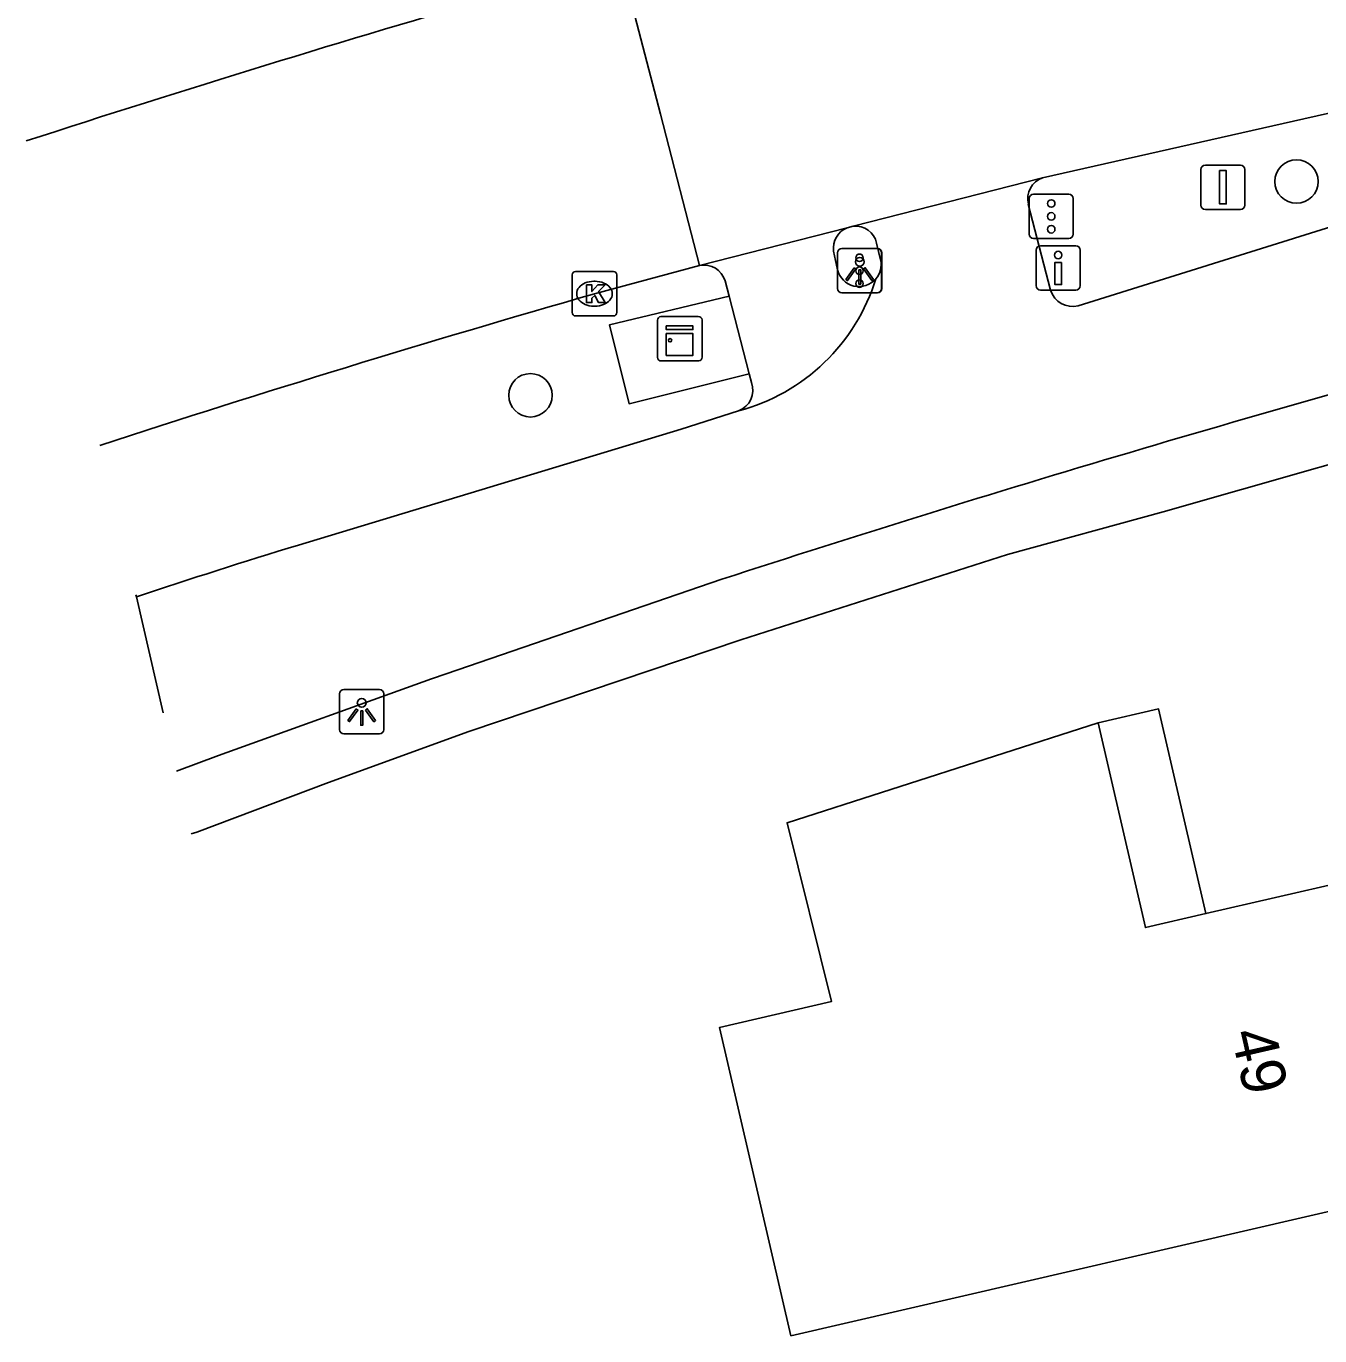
# Model space of a CAD drawing. Extents: x 156414 to 157775, y 382335 to 383765.
# Drawn here: x 156630.05 to 156659.19, y 382874.07 to 382903.56 of the extents above; entities that cross this region are included whole.
import ezdxf

# ---------------------------------------------------------------- set-up
doc = ezdxf.new("R2010")
doc.units = 0
for name, color, linetype in [('IMGEO_Boom', 7, 'Continuous'), ('IMGEO_Drukknoppaal', 7, 'Continuous'), ('IMGEO_Fietspad_gesloten', 7, 'Continuous'), ('IMGEO_Kast', 7, 'Continuous'), ('IMGEO_Kolk', 7, 'Continuous'), ('IMGEO_Lichtpunt', 7, 'Continuous'), ('IMGEO_OVBaan_gesloten', 7, 'Continuous'), ('IMGEO_Pand', 7, 'Continuous'), ('IMGEO_Pand_nummerreeks', 7, 'Continuous'), ('IMGEO_Pand_overbouw', 7, 'Continuous'), ('IMGEO_Verkeersbordpaal', 7, 'Continuous'), ('IMGEO_Verkeersregelinstallatiepaal', 7, 'Continuous'), ('IMGEO_Voetpad_open', 7, 'Continuous')]:
    doc.layers.add(name, color=color, linetype=linetype)

msp = doc.modelspace()

# ---------------------------------------------------------------- linework, layer by layer
at = {"layer": 'IMGEO_Boom'}
for centre in [(156658.661, 382900.059), (156641.409, 382895.246)]:
    msp.add_circle(centre, 0.489, dxfattribs=at)
at = {"layer": 'IMGEO_Drukknoppaal'}
for p, q in [((156652.799, 382897.715), (156652.799, 382898.515)), ((156652.799, 382898.515), (156652.799, 382897.715)), ((156652.899, 382898.615), (156653.689, 382898.615)), ((156653.689, 382898.615), (156652.899, 382898.615)), ((156653.789, 382898.515), (156653.789, 382897.715)), ((156653.789, 382897.715), (156653.789, 382898.515)), ((156653.689, 382897.615), (156652.899, 382897.615)), ((156652.899, 382897.615), (156653.689, 382897.615))]:
    msp.add_line(p, q, dxfattribs=at)
msp.add_lwpolyline([(156653.369, 382898.24), (156653.369, 382897.74), (156653.219, 382897.74), (156653.219, 382898.24), (156653.369, 382898.24)], dxfattribs=at)
msp.add_circle((156653.294, 382898.405), 0.085, dxfattribs=at)
for centre, start, end in [((156652.899, 382898.515), 90, 180), ((156652.899, 382898.515), 90, 180), ((156653.689, 382898.515), 0, 90), ((156653.689, 382898.515), 360, 90), ((156652.899, 382897.715), 180, 270), ((156652.899, 382897.715), 180, 270), ((156653.689, 382897.715), 270, 0), ((156653.689, 382897.715), 270, 0)]:
    msp.add_arc(centre, 0.1, start, end, dxfattribs=at)
at = {"layer": 'IMGEO_Fietspad_gesloten'}
for points in [[(156667.356, 382901.52), (156653.745, 382897.261)], [(156653.124, 382897.612), (156652.622, 382899.55)], [(156649.206, 382898.672), (156649.296, 382898.294)], [(156646.098, 382894.894), (156644.805, 382894.481), (156636.186, 382891.875)], [(156633.442, 382886.785), (156634.383, 382887.139), (156639.183, 382888.859), (156639.511, 382888.974), (156645.723, 382891.105)], [(156632.536, 382890.706), (156632.525, 382890.752)], [(156632.536, 382890.706), (156633.139, 382888.095)]]:
    msp.add_lwpolyline(points, dxfattribs=at)
for centre, radius, start, end in [((156653.113, 382899.669), 0.505, 109.9269, 193.5983), ((156648.722, 382898.559), 0.497, 13.1695, 94.8535), ((156648.807, 382898.193), 0.5, 319.7399, 11.6794), ((156644.961, 382899.167), 4.421, 284.9015, 342.9452), ((156653.618, 382897.761), 0.516, 196.8081, 284.2401), ((156758.708, 382543.808), 365.213, 105.00057, 108.02104), ((156677.031, 382758.061), 139.909, 106.97411, 108.54371)]:
    msp.add_arc(centre, radius, start, end, dxfattribs=at)
at = {"layer": 'IMGEO_Kast'}
for p, q in [((156644.274, 382896.095), (156644.274, 382896.936)), ((156644.274, 382896.936), (156644.274, 382896.095)), ((156644.349, 382897.02), (156645.19, 382897.02)), ((156645.19, 382897.02), (156644.349, 382897.02)), ((156645.274, 382896.945), (156645.274, 382896.104)), ((156645.274, 382896.104), (156645.274, 382896.945)), ((156645.199, 382896.02), (156644.358, 382896.02)), ((156644.358, 382896.02), (156645.199, 382896.02))]:
    msp.add_line(p, q, dxfattribs=at)
for points in [[(156644.469, 382896.81), (156645.069, 382896.81), (156645.069, 382896.725), (156644.469, 382896.725), (156644.469, 382896.81)], [(156644.469, 382896.635), (156645.069, 382896.635), (156645.069, 382896.146), (156644.469, 382896.146), (156644.469, 382896.635)]]:
    msp.add_lwpolyline(points, dxfattribs=at)
msp.add_circle((156644.553, 382896.484), 0.0377, dxfattribs=at)
for centre, start, end in [((156644.352, 382896.942), 92.4484, 184.2845), ((156644.352, 382896.942), 92.4484, 184.2845), ((156645.196, 382896.942), 2.4484, 94.2845), ((156645.196, 382896.942), 2.4484, 94.2845), ((156644.352, 382896.098), 182.4484, 274.2845), ((156644.352, 382896.098), 182.4484, 274.2845), ((156645.196, 382896.098), 272.4484, 4.2845), ((156645.196, 382896.098), 272.4484, 4.2845)]:
    msp.add_arc(centre, 0.0779, start, end, dxfattribs=at)
at = {"layer": 'IMGEO_Kolk'}
for p, q in [((156642.351, 382897.107), (156642.351, 382897.959)), ((156642.426, 382898.033), (156643.278, 382898.033)), ((156643.352, 382897.959), (156643.352, 382897.107)), ((156642.839, 382897.813), (156642.864, 382897.813)), ((156643.278, 382897.033), (156642.426, 382897.033)), ((156642.862, 382897.253), (156642.837, 382897.253))]:
    msp.add_line(p, q, dxfattribs=at)
for points in [[(156642.351, 382897.107), (156642.351, 382897.959)], [(156642.426, 382898.033), (156643.278, 382898.033)], [(156643.352, 382897.959), (156643.352, 382897.107)], [(156642.672, 382897.733), (156642.795, 382897.733), (156642.795, 382897.582), (156642.925, 382897.733), (156643.089, 382897.733), (156642.943, 382897.582), (156643.096, 382897.333), (156642.944, 382897.333), (156642.859, 382897.497), (156642.795, 382897.43), (156642.795, 382897.333), (156642.672, 382897.333), (156642.672, 382897.733)], [(156643.278, 382897.033), (156642.426, 382897.033)]]:
    msp.add_lwpolyline(points, dxfattribs=at)
for centre, start, end in [((156642.428, 382897.957), 91.552, 178.448), ((156642.428, 382897.957), 91.552, 178.448), ((156643.276, 382897.957), 1.552, 88.448), ((156643.276, 382897.957), 1.552, 88.448), ((156642.428, 382897.109), 181.552, 268.448), ((156642.428, 382897.109), 181.552, 268.448), ((156643.276, 382897.109), 271.552, 358.448), ((156643.276, 382897.109), 271.552, 358.448)]:
    msp.add_arc(centre, 0.0765, start, end, dxfattribs=at)
for centre, major_axis, ratio, start_param, end_param in [((156642.838, 382897.533), (-0.387, 0.002), 0.722429, 4.712389, 7.853982), ((156642.863, 382897.533), (-0.39, 0.002), 0.717154, 1.570796, 4.712389)]:
    msp.add_ellipse(centre, major_axis=major_axis, ratio=ratio, start_param=start_param, end_param=end_param, dxfattribs=at)
at = {"layer": 'IMGEO_Lichtpunt'}
for p, q in [((156649.229, 382898.55), (156648.421, 382898.55)), ((156649.229, 382898.55), (156648.421, 382898.55)), ((156648.327, 382898.455), (156648.327, 382897.648)), ((156648.327, 382898.455), (156648.327, 382897.648)), ((156649.323, 382897.648), (156649.323, 382898.455)), ((156649.323, 382897.648), (156649.323, 382898.455)), ((156648.421, 382897.554), (156649.229, 382897.554)), ((156648.421, 382897.554), (156649.229, 382897.554)), ((156637.112, 382888.524), (156637.112, 382887.717)), ((156637.112, 382888.524), (156637.112, 382887.717)), ((156638.014, 382888.619), (156637.206, 382888.619)), ((156638.014, 382888.619), (156637.206, 382888.619)), ((156638.108, 382887.717), (156638.108, 382888.524)), ((156638.108, 382887.717), (156638.108, 382888.524)), ((156637.206, 382887.623), (156638.014, 382887.623)), ((156637.206, 382887.623), (156638.014, 382887.623))]:
    msp.add_line(p, q, dxfattribs=at)
for points in [[(156648.701, 382898.119), (156648.74, 382898.091), (156648.552, 382897.829), (156648.514, 382897.856), (156648.701, 382898.119)], [(156648.803, 382898.071), (156648.85, 382898.071), (156648.85, 382897.749), (156648.803, 382897.749), (156648.803, 382898.071)], [(156648.913, 382898.091), (156648.951, 382898.118), (156649.138, 382897.856), (156649.099, 382897.828), (156648.913, 382898.091)], [(156637.486, 382888.188), (156637.525, 382888.16), (156637.337, 382887.898), (156637.299, 382887.925), (156637.486, 382888.188)], [(156637.698, 382888.16), (156637.736, 382888.187), (156637.923, 382887.925), (156637.884, 382887.897), (156637.698, 382888.16)], [(156637.588, 382888.14), (156637.635, 382888.14), (156637.635, 382887.818), (156637.588, 382887.818), (156637.588, 382888.14)]]:
    msp.add_lwpolyline(points, dxfattribs=at)
for centre in [(156648.826, 382898.253), (156637.611, 382888.322)]:
    msp.add_circle(centre, 0.0994, dxfattribs=at)
for centre, start, end in [((156648.421, 382898.455), 90, 180), ((156648.421, 382898.455), 90, 180), ((156649.229, 382898.455), 0, 90), ((156649.229, 382898.455), 0, 90), ((156648.421, 382897.648), 180, 270), ((156648.421, 382897.648), 180, 270), ((156649.229, 382897.648), 270, 0), ((156649.229, 382897.648), 270, 360), ((156637.206, 382888.524), 90, 180), ((156637.206, 382888.524), 90, 180), ((156638.014, 382888.524), 0, 90), ((156638.014, 382888.524), 0, 90), ((156637.206, 382887.717), 180, 270), ((156637.206, 382887.717), 180, 270), ((156638.014, 382887.717), 270, 0), ((156638.014, 382887.717), 270, 360)]:
    msp.add_arc(centre, 0.0946, start, end, dxfattribs=at)
at = {"layer": 'IMGEO_OVBaan_gesloten'}
for points in [[(156645.22, 382898.169), (156644.336, 382901.573), (156643.451, 382904.977)], [(156652.941, 382900.144), (156665.009, 382902.868), (156666.837, 382903.33)], [(156652.941, 382900.144), (156648.68, 382899.054)], [(156645.22, 382898.169), (156648.544, 382899.02)], [(156648.544, 382899.02), (156648.68, 382899.054)], [(156642.851, 382897.534), (156645.22, 382898.169)]]:
    msp.add_lwpolyline(points, dxfattribs=at)
for centre, radius, start, end in [((156740.59, 382560.514), 357.953, 106.18271, 107.98685), ((156734.846, 382577.572), 332.924, 106.04089, 108.04621)]:
    msp.add_arc(centre, radius, start, end, dxfattribs=at)
at = {"layer": 'IMGEO_Pand'}
msp.add_lwpolyline([(156647.271, 382874.069), (156645.666, 382881.009), (156648.189, 382881.593), (156647.19, 382885.623), (156654.192, 382887.871), (156655.257, 382883.262), (156656.621, 382883.577), (156659.759, 382884.302), (156661.361, 382877.323), (156647.271, 382874.069)], dxfattribs=at)
at = {"layer": 'IMGEO_Pand_overbouw'}
msp.add_lwpolyline([(156654.192, 382887.871), (156655.257, 382883.262), (156656.621, 382883.577), (156655.556, 382888.186)], close=True, dxfattribs=at)
at = {"layer": 'IMGEO_Verkeersbordpaal'}
for p, q in [((156656.508, 382899.53), (156656.508, 382900.33)), ((156656.508, 382900.33), (156656.508, 382899.53)), ((156656.608, 382900.43), (156657.398, 382900.43)), ((156657.398, 382900.43), (156656.608, 382900.43)), ((156657.498, 382900.33), (156657.498, 382899.53)), ((156657.498, 382899.53), (156657.498, 382900.33)), ((156657.398, 382899.43), (156656.608, 382899.43)), ((156656.608, 382899.43), (156657.398, 382899.43))]:
    msp.add_line(p, q, dxfattribs=at)
msp.add_lwpolyline([(156656.928, 382900.305), (156657.078, 382900.305), (156657.078, 382899.555), (156656.928, 382899.555), (156656.928, 382900.305)], dxfattribs=at)
for centre, start, end in [((156656.608, 382900.33), 90, 180), ((156656.608, 382900.33), 90, 180), ((156657.398, 382900.33), 0, 90), ((156657.398, 382900.33), 360, 90), ((156656.608, 382899.53), 180, 270), ((156656.608, 382899.53), 180, 270), ((156657.398, 382899.53), 270, 0), ((156657.398, 382899.53), 270, 0)]:
    msp.add_arc(centre, 0.1, start, end, dxfattribs=at)
at = {"layer": 'IMGEO_Verkeersregelinstallatiepaal'}
for p, q in [((156652.742, 382899.775), (156653.532, 382899.775)), ((156653.532, 382899.775), (156652.742, 382899.775)), ((156652.642, 382898.875), (156652.642, 382899.675)), ((156652.642, 382899.675), (156652.642, 382898.875)), ((156653.632, 382899.675), (156653.632, 382898.875)), ((156653.632, 382898.875), (156653.632, 382899.675)), ((156648.425, 382898.552), (156649.215, 382898.552)), ((156649.215, 382898.552), (156648.425, 382898.552)), ((156653.532, 382898.775), (156652.742, 382898.775)), ((156652.742, 382898.775), (156653.532, 382898.775)), ((156648.325, 382897.652), (156648.325, 382898.452)), ((156648.325, 382898.452), (156648.325, 382897.652)), ((156649.315, 382898.452), (156649.315, 382897.652)), ((156649.315, 382897.652), (156649.315, 382898.452)), ((156649.215, 382897.552), (156648.425, 382897.552)), ((156648.425, 382897.552), (156649.215, 382897.552))]:
    msp.add_line(p, q, dxfattribs=at)
for centre in [(156653.137, 382899.565), (156653.137, 382899.275), (156653.137, 382898.985), (156648.82, 382898.342), (156648.82, 382898.052), (156648.82, 382897.762)]:
    msp.add_circle(centre, 0.085, dxfattribs=at)
for centre, start, end in [((156652.742, 382899.675), 90, 180), ((156652.742, 382899.675), 90, 180), ((156653.532, 382899.675), 0, 90), ((156653.532, 382899.675), 360, 90), ((156652.742, 382898.875), 180, 270), ((156652.742, 382898.875), 180, 270), ((156653.532, 382898.875), 270, 0), ((156653.532, 382898.875), 270, 0), ((156648.425, 382898.452), 90, 180), ((156648.425, 382898.452), 90, 180), ((156649.215, 382898.452), 0, 90), ((156649.215, 382898.452), 360, 90), ((156648.425, 382897.652), 180, 270), ((156648.425, 382897.652), 180, 270), ((156649.215, 382897.652), 270, 0), ((156649.215, 382897.652), 270, 0)]:
    msp.add_arc(centre, 0.1, start, end, dxfattribs=at)
at = {"layer": 'IMGEO_Voetpad_open'}
for points in [[(156648.237, 382898.492), (156648.322, 382898.072)], [(156645.882, 382897.476), (156645.793, 382897.821)], [(156646.336, 382895.731), (156643.633, 382895.057), (156643.189, 382896.831), (156645.882, 382897.476)], [(156645.882, 382897.476), (156646.336, 382895.731)], [(156646.387, 382895.534), (156646.336, 382895.731)], [(156662.663, 382894.621), (156655.658, 382892.624), (156652.152, 382891.665), (156646.148, 382889.742), (156640.021, 382887.678), (156636.864, 382886.529), (156633.896, 382885.409), (156633.769, 382885.37)]]:
    msp.add_lwpolyline(points, dxfattribs=at)
for centre, radius, start, end in [((156648.732, 382898.558), 0.499, 112.0855, 187.5637), ((156645.317, 382897.684), 0.495, 16.1051, 101.3518), ((156648.807, 382898.193), 0.499, 193.9706, 319.7697), ((156645.918, 382895.36), 0.5, 291.0623, 20.3334)]:
    msp.add_arc(centre, radius, start, end, dxfattribs=at)

# ---------------------------------------------------------------- texts
at = {"layer": 'IMGEO_Pand_nummerreeks'}
msp.add_text('49', height=1, rotation=282.928, dxfattribs=at).set_placement((156657.178, 382880.885))

doc.saveas('drawing.dxf')
